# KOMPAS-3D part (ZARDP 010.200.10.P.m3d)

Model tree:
1. Плоскость XY
2. Плоскость ZX
3. Плоскость ZY
4. Ось X
5. Ось Y
6. Ось Z
7. Начало координат
8. Смещенная плоскость:1
     Расстояние = 100
9. Смещенная плоскость:2
     Расстояние = 100
10. Булева операция:3
11. Булева операция:4
